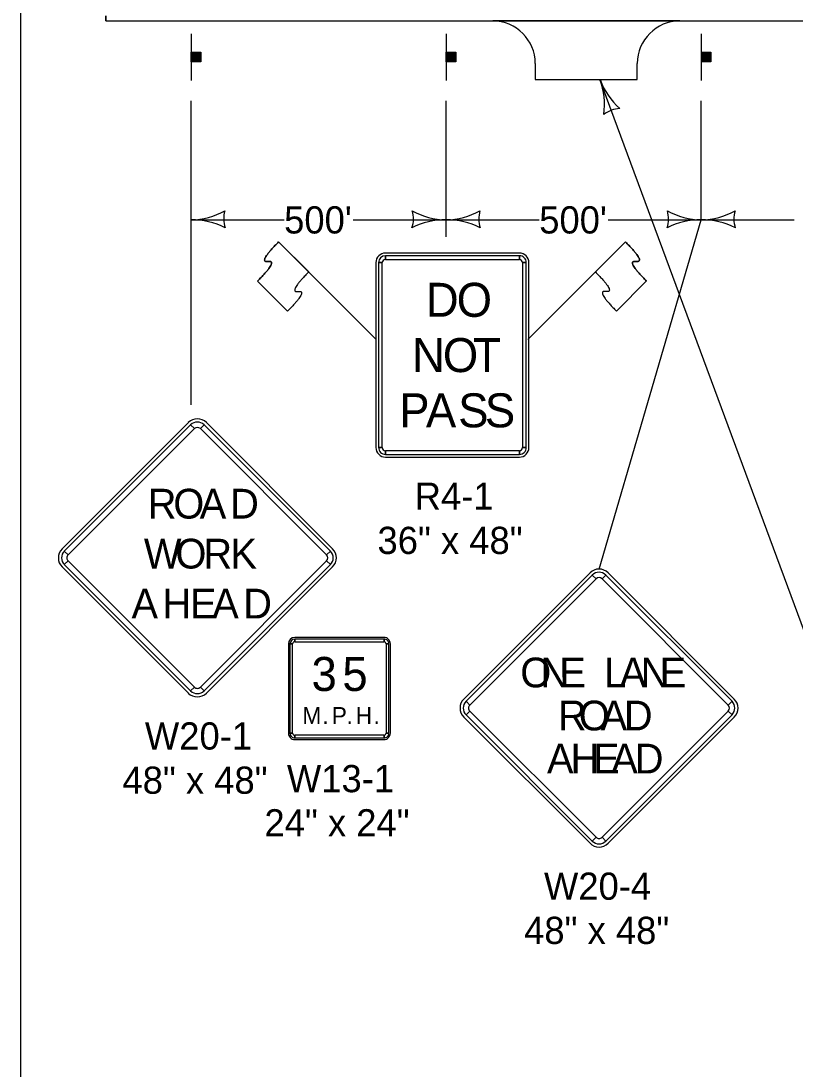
# Model space of a CAD drawing. Extents: x -2134934 to -2119606, y -2139046 to -2137036.
# Drawn here: x -2134934 to -2134479, y -2138285 to -2137668 of the extents above; entities that cross this region are included whole.
import ezdxf

# ---------------------------------------------------------------- set-up
doc = ezdxf.new("R2010")
doc.units = 0
for name, color, linetype in [('Default', 7, 'Continuous'), ('dsnCellElements', 7, 'Continuous'), ('dsnStdLabel', 7, 'Continuous'), ('dsnStdLineWork', 7, 'Continuous'), ('Level 2', 7, 'Continuous'), ('Level 5', 7, 'Continuous')]:
    doc.layers.add(name, color=color, linetype=linetype)

msp = doc.modelspace()

# ---------------------------------------------------------------- linework, layer by layer
at = {"layer": 'Default'}
msp.add_lwpolyline([(-2134934.44, -2137035.95), (-2131799.45, -2137035.95), (-2131799.45, -2139045.94), (-2134934.44, -2139045.94)], close=True, dxfattribs=at)
at = {"layer": 'dsnCellElements'}
for centre, radius, start, end in [((-2134633.81, -2137717.39), 42.5, 352.23545, 20.30794), ((-2134554.09, -2137687.89), 42.5, 200.30794, 228.38043), ((-2134581.58, -2137736.06), 16.42, 92.57459, 128.04129)]:
    msp.add_arc(centre, radius, start, end, dxfattribs=at)
at = {"layer": 'dsnStdLabel'}
for p, q in [((-2134725.6, -2137855.42), (-2134782.94, -2137798.12)), ((-2134782.94, -2137798.12), (-2134765.25, -2137815.8)), ((-2134636.31, -2137855.42), (-2134578.99, -2137798.11)), ((-2134578.99, -2137798.11), (-2134596.67, -2137815.79)), ((-2134641.36, -2137804.67), (-2134720.11, -2137804.67)), ((-2134720.11, -2137808.42), (-2134720.11, -2137806.23)), ((-2134641.36, -2137806.23), (-2134641.36, -2137808.42)), ((-2134725.73, -2137810.29), (-2134725.73, -2137919.04)), ((-2134724.17, -2137810.29), (-2134721.98, -2137810.29)), ((-2134639.48, -2137810.29), (-2134637.3, -2137810.29)), ((-2134635.73, -2137919.04), (-2134635.73, -2137810.29)), ((-2134777.63, -2137838.79), (-2134795.31, -2137821.12)), ((-2134584.29, -2137838.78), (-2134566.61, -2137821.1)), ((-2134836.02, -2137904.4), (-2134910.27, -2137978.64)), ((-2134834.69, -2137905.72), (-2134832.48, -2137907.93)), ((-2134828.95, -2137907.93), (-2134826.74, -2137905.72)), ((-2134751.17, -2137978.64), (-2134825.41, -2137904.4)), ((-2134721.98, -2137919.04), (-2134724.17, -2137919.04)), ((-2134637.3, -2137919.04), (-2134639.48, -2137919.04)), ((-2134720.11, -2137923.1), (-2134720.11, -2137920.91)), ((-2134720.11, -2137924.66), (-2134641.36, -2137924.66)), ((-2134641.36, -2137920.91), (-2134641.36, -2137923.1)), ((-2134906.73, -2137982.18), (-2134908.94, -2137979.97)), ((-2134752.49, -2137979.97), (-2134754.7, -2137982.18)), ((-2134908.94, -2137987.92), (-2134906.73, -2137985.71)), ((-2134754.7, -2137985.71), (-2134752.49, -2137987.92)), ((-2134910.27, -2137989.25), (-2134836.02, -2138063.5)), ((-2134825.41, -2138063.5), (-2134751.17, -2137989.25)), ((-2134599.82, -2137992.73), (-2134674.07, -2138066.98)), ((-2134514.97, -2138066.98), (-2134589.22, -2137992.73)), ((-2134598.5, -2137994.06), (-2134596.29, -2137996.27)), ((-2134592.75, -2137996.27), (-2134590.54, -2137994.06)), ((-2134777.2, -2138034.52), (-2134777.2, -2138087.02)), ((-2134776.26, -2138034.52), (-2134774.7, -2138034.52)), ((-2134720.95, -2138030.77), (-2134773.45, -2138030.77)), ((-2134773.45, -2138033.27), (-2134773.45, -2138031.71)), ((-2134720.95, -2138031.71), (-2134720.95, -2138033.27)), ((-2134719.7, -2138034.52), (-2134718.13, -2138034.52)), ((-2134717.2, -2138087.02), (-2134717.2, -2138034.52)), ((-2134832.48, -2138059.96), (-2134834.69, -2138062.17)), ((-2134826.74, -2138062.17), (-2134828.95, -2138059.96)), ((-2134670.54, -2138070.51), (-2134672.74, -2138068.31)), ((-2134516.3, -2138068.31), (-2134518.51, -2138070.51)), ((-2134674.07, -2138077.59), (-2134599.82, -2138151.83)), ((-2134672.74, -2138076.26), (-2134670.54, -2138074.05)), ((-2134589.22, -2138151.83), (-2134514.97, -2138077.59)), ((-2134518.51, -2138074.05), (-2134516.3, -2138076.26)), ((-2134774.7, -2138087.02), (-2134776.26, -2138087.02)), ((-2134773.45, -2138089.83), (-2134773.45, -2138088.27)), ((-2134773.45, -2138090.77), (-2134720.95, -2138090.77)), ((-2134720.95, -2138088.27), (-2134720.95, -2138089.83)), ((-2134718.13, -2138087.02), (-2134719.7, -2138087.02)), ((-2134596.29, -2138148.3), (-2134598.5, -2138150.51)), ((-2134590.54, -2138150.51), (-2134592.75, -2138148.3))]:
    msp.add_line(p, q, dxfattribs=at)
for points in [[(-2134641.36, -2137806.23), (-2134720.11, -2137806.23), (-2134720.11, -2137808.42), (-2134641.36, -2137808.42), (-2134641.36, -2137806.23)], [(-2134724.17, -2137810.29), (-2134724.17, -2137919.04), (-2134721.98, -2137919.04), (-2134721.98, -2137810.29), (-2134724.17, -2137810.29)], [(-2134637.3, -2137919.04), (-2134637.3, -2137810.29), (-2134639.48, -2137810.29), (-2134639.48, -2137919.04), (-2134637.3, -2137919.04)], [(-2134834.69, -2137905.72), (-2134908.94, -2137979.97), (-2134906.73, -2137982.18), (-2134832.48, -2137907.93), (-2134834.69, -2137905.72)], [(-2134752.49, -2137979.97), (-2134826.74, -2137905.72), (-2134828.95, -2137907.93), (-2134754.7, -2137982.18), (-2134752.49, -2137979.97)], [(-2134720.11, -2137923.1), (-2134641.36, -2137923.1), (-2134641.36, -2137920.91), (-2134720.11, -2137920.91), (-2134720.11, -2137923.1)], [(-2134908.94, -2137987.92), (-2134834.69, -2138062.17), (-2134832.48, -2138059.96), (-2134906.73, -2137985.71), (-2134908.94, -2137987.92)], [(-2134826.74, -2138062.17), (-2134752.49, -2137987.92), (-2134754.7, -2137985.71), (-2134828.95, -2138059.96), (-2134826.74, -2138062.17)], [(-2134598.5, -2137994.06), (-2134672.74, -2138068.31), (-2134670.54, -2138070.51), (-2134596.29, -2137996.27), (-2134598.5, -2137994.06)], [(-2134516.3, -2138068.31), (-2134590.54, -2137994.06), (-2134592.75, -2137996.27), (-2134518.51, -2138070.51), (-2134516.3, -2138068.31)], [(-2134776.26, -2138034.52), (-2134776.26, -2138087.02), (-2134774.7, -2138087.02), (-2134774.7, -2138034.52), (-2134776.26, -2138034.52)], [(-2134720.95, -2138031.71), (-2134773.45, -2138031.71), (-2134773.45, -2138033.27), (-2134720.95, -2138033.27), (-2134720.95, -2138031.71)], [(-2134718.13, -2138087.02), (-2134718.13, -2138034.52), (-2134719.7, -2138034.52), (-2134719.7, -2138087.02), (-2134718.13, -2138087.02)], [(-2134672.74, -2138076.26), (-2134598.5, -2138150.51), (-2134596.29, -2138148.3), (-2134670.54, -2138074.05), (-2134672.74, -2138076.26)], [(-2134590.54, -2138150.51), (-2134516.3, -2138076.26), (-2134518.51, -2138074.05), (-2134592.75, -2138148.3), (-2134590.54, -2138150.51)], [(-2134773.45, -2138089.83), (-2134720.95, -2138089.83), (-2134720.95, -2138088.27), (-2134773.45, -2138088.27), (-2134773.45, -2138089.83)]]:
    msp.add_lwpolyline(points, close=True, dxfattribs=at)
for centre, radius, start, end in [((-2134720.11, -2137810.29), 5.62, 90.00021, 179.99985), ((-2134720.11, -2137810.29), 4.06, 90.00021, 179.99985), ((-2134720.11, -2137810.29), 1.87, 90.00021, 179.99985), ((-2134641.36, -2137810.29), 5.62, 0, 90.00021), ((-2134641.36, -2137810.29), 4.06, 0, 90.00021), ((-2134641.36, -2137810.29), 1.87, 0, 90.00021), ((-2134830.72, -2137909.7), 7.5, 44.99999, 134.99974), ((-2134830.72, -2137909.7), 5.62, 44.99999, 134.99974), ((-2134830.72, -2137909.7), 2.5, 44.99999, 134.99974), ((-2134720.11, -2137919.04), 5.62, 179.99985, 270.00006), ((-2134720.11, -2137919.04), 4.06, 179.99985, 270.00006), ((-2134720.11, -2137919.04), 1.87, 179.99985, 270.00006), ((-2134641.36, -2137919.04), 5.62, 270.00006, 0.00027), ((-2134641.36, -2137919.04), 4.06, 270.00006, 0.00027), ((-2134641.36, -2137919.04), 1.87, 270.00006, 0.00027), ((-2134904.96, -2137983.95), 7.5, 134.99974, 224.99995), ((-2134904.96, -2137983.95), 5.62, 134.99974, 224.99995), ((-2134756.47, -2137983.95), 5.62, 315.00016, 44.9998), ((-2134756.47, -2137983.95), 7.5, 315.00016, 44.9998), ((-2134904.96, -2137983.95), 2.5, 134.99974, 224.99995), ((-2134756.47, -2137983.95), 2.5, 315.00016, 44.9998), ((-2134594.52, -2137998.04), 7.5, 44.99999, 134.99974), ((-2134594.52, -2137998.04), 5.62, 44.99999, 134.99974), ((-2134594.52, -2137998.04), 2.5, 44.99999, 134.99974), ((-2134773.45, -2138034.52), 3.75, 90.00021, 179.99985), ((-2134773.45, -2138034.52), 2.81, 90.00021, 179.99985), ((-2134773.45, -2138034.52), 1.25, 90.00021, 179.99985), ((-2134720.95, -2138034.52), 3.75, 0, 90.00021), ((-2134720.95, -2138034.52), 2.81, 0, 90.00021), ((-2134720.95, -2138034.52), 1.25, 0, 90.00021), ((-2134830.72, -2138058.19), 2.5, 224.99995, 315.00016), ((-2134830.72, -2138058.19), 7.5, 224.99995, 315.00016), ((-2134830.72, -2138058.19), 5.62, 224.99995, 315.00016), ((-2134668.77, -2138072.28), 7.5, 134.99974, 224.99995), ((-2134520.28, -2138072.28), 7.5, 315.00016, 44.9998), ((-2134668.77, -2138072.28), 5.62, 134.99974, 224.99995), ((-2134668.77, -2138072.28), 2.5, 134.99974, 224.99995), ((-2134520.28, -2138072.28), 2.5, 315.00016, 44.9998), ((-2134520.28, -2138072.28), 5.62, 315.00016, 44.9998), ((-2134773.45, -2138087.02), 3.75, 179.99985, 270.00006), ((-2134773.45, -2138087.02), 2.81, 179.99985, 270.00006), ((-2134773.45, -2138087.02), 1.25, 179.99985, 270.00006), ((-2134720.95, -2138087.02), 3.75, 270.00006, 0.00027), ((-2134720.95, -2138087.02), 2.81, 270.00006, 0.00027), ((-2134720.95, -2138087.02), 1.25, 270.00006, 0.00027), ((-2134594.52, -2138146.53), 7.5, 224.99995, 315.00016), ((-2134594.52, -2138146.53), 5.62, 224.99995, 315.00016), ((-2134594.52, -2138146.53), 2.5, 224.99995, 315.00016)]:
    msp.add_arc(centre, radius, start, end, dxfattribs=at)
for points in [[(-2134795.31, -2137821.12), (-2134782.93, -2137808.74), (-2134795.31, -2137810.51), (-2134782.94, -2137798.12)], [(-2134566.61, -2137821.1), (-2134578.99, -2137808.72), (-2134566.61, -2137810.49), (-2134578.99, -2137798.11)], [(-2134765.25, -2137815.8), (-2134777.62, -2137828.19), (-2134765.25, -2137826.41), (-2134777.63, -2137838.79)], [(-2134596.67, -2137815.79), (-2134584.29, -2137828.17), (-2134596.66, -2137826.4), (-2134584.29, -2137838.78)]]:
    msp.add_open_spline(points, degree=2, dxfattribs=at)
at = {"layer": 'dsnStdLineWork'}
for p, q in [((-2134884.44, -2137668.16), (-2134884.44, -2137665.16)), ((-2134884.44, -2137665.16), (-2134884.44, -2137668.16)), ((-2134884.44, -2137668.16), (-2133384.44, -2137668.16)), ((-2134884.44, -2137668.16), (-2133384.44, -2137668.16))]:
    msp.add_line(p, q, dxfattribs=at)
at = {"layer": 'Level 2'}
for p, q in [((-2134547.02, -2137668.16), (-2134657.02, -2137668.16)), ((-2134834.44, -2137675.66), (-2134834.44, -2137703.16)), ((-2134684.44, -2137675.66), (-2134684.44, -2137703.16)), ((-2134534.44, -2137675.66), (-2134534.44, -2137703.16)), ((-2134834.03, -2137692.11), (-2134834.03, -2137686.52)), ((-2134833.75, -2137686.52), (-2134833.75, -2137692.11)), ((-2134833.48, -2137692.11), (-2134833.48, -2137686.52)), ((-2134833.22, -2137686.52), (-2134833.22, -2137692.11)), ((-2134833, -2137692.11), (-2134833, -2137686.52)), ((-2134832.79, -2137686.52), (-2134832.79, -2137692.11)), ((-2134832.45, -2137692.11), (-2134832.45, -2137686.52)), ((-2134832.19, -2137686.52), (-2134832.19, -2137692.11)), ((-2134831.96, -2137692.11), (-2134831.98, -2137686.52)), ((-2134831.65, -2137686.52), (-2134831.65, -2137692.11)), ((-2134831.27, -2137692.11), (-2134831.27, -2137686.52)), ((-2134830.84, -2137686.52), (-2134830.84, -2137692.11)), ((-2134830.61, -2137692.11), (-2134830.63, -2137686.52)), ((-2134830.2, -2137686.52), (-2134830.18, -2137692.11)), ((-2134829.98, -2137692.11), (-2134829.98, -2137686.52)), ((-2134829.66, -2137686.52), (-2134829.66, -2137692.11)), ((-2134829.43, -2137692.11), (-2134829.43, -2137686.52)), ((-2134829.11, -2137686.52), (-2134829.11, -2137692.11)), ((-2134684.03, -2137692.11), (-2134684.03, -2137686.52)), ((-2134683.75, -2137686.52), (-2134683.75, -2137692.11)), ((-2134683.48, -2137692.11), (-2134683.48, -2137686.52)), ((-2134683.22, -2137686.52), (-2134683.22, -2137692.11)), ((-2134683, -2137692.11), (-2134683, -2137686.52)), ((-2134682.79, -2137686.52), (-2134682.79, -2137692.11)), ((-2134682.45, -2137692.11), (-2134682.45, -2137686.52)), ((-2134682.19, -2137686.52), (-2134682.19, -2137692.11)), ((-2134681.97, -2137692.11), (-2134681.98, -2137686.52)), ((-2134681.65, -2137686.52), (-2134681.65, -2137692.11)), ((-2134681.27, -2137692.11), (-2134681.27, -2137686.52)), ((-2134680.84, -2137686.52), (-2134680.84, -2137692.11)), ((-2134680.62, -2137692.11), (-2134680.63, -2137686.52)), ((-2134680.2, -2137686.52), (-2134680.18, -2137692.11)), ((-2134679.98, -2137692.11), (-2134679.98, -2137686.52)), ((-2134679.66, -2137686.52), (-2134679.66, -2137692.11)), ((-2134679.43, -2137692.11), (-2134679.43, -2137686.52)), ((-2134679.12, -2137686.52), (-2134679.12, -2137692.11)), ((-2134534.03, -2137692.11), (-2134534.03, -2137686.52)), ((-2134533.75, -2137686.52), (-2134533.75, -2137692.11)), ((-2134533.48, -2137692.11), (-2134533.48, -2137686.52)), ((-2134533.22, -2137686.52), (-2134533.22, -2137692.11)), ((-2134533, -2137692.11), (-2134533, -2137686.52)), ((-2134532.79, -2137686.52), (-2134532.79, -2137692.11)), ((-2134532.45, -2137692.11), (-2134532.45, -2137686.52)), ((-2134532.19, -2137686.52), (-2134532.19, -2137692.11)), ((-2134531.97, -2137692.11), (-2134531.98, -2137686.52)), ((-2134531.65, -2137686.52), (-2134531.65, -2137692.11)), ((-2134531.27, -2137692.11), (-2134531.27, -2137686.52)), ((-2134530.84, -2137686.52), (-2134530.84, -2137692.11)), ((-2134530.62, -2137692.11), (-2134530.63, -2137686.52)), ((-2134530.2, -2137686.52), (-2134530.18, -2137692.11)), ((-2134529.98, -2137692.11), (-2134529.98, -2137686.52)), ((-2134529.66, -2137686.52), (-2134529.66, -2137692.11)), ((-2134529.43, -2137692.11), (-2134529.43, -2137686.52)), ((-2134529.12, -2137686.52), (-2134529.12, -2137692.11)), ((-2134399.95, -2138226.87), (-2134593.95, -2137702.64)), ((-2134834.44, -2137893.97), (-2134834.44, -2137715.16)), ((-2134684.44, -2137795.16), (-2134684.44, -2137715.16)), ((-2134534.44, -2137785.16), (-2134534.44, -2137715.16)), ((-2134834.44, -2137785.16), (-2134779.69, -2137785.16)), ((-2134739.19, -2137785.16), (-2134684.44, -2137785.16)), ((-2134684.44, -2137785.16), (-2134629.69, -2137785.16)), ((-2134594.52, -2137990.54), (-2134534.44, -2137785.16)), ((-2134589.19, -2137785.16), (-2134534.44, -2137785.16)), ((-2134534.44, -2137785.16), (-2134479.69, -2137785.16))]:
    msp.add_line(p, q, dxfattribs=at)
for points in [[(-2134834.35, -2137692.11), (-2134834.35, -2137686.48), (-2134828.72, -2137686.48), (-2134828.72, -2137692.11)], [(-2134684.35, -2137692.11), (-2134684.35, -2137686.48), (-2134678.72, -2137686.48), (-2134678.72, -2137692.11)], [(-2134534.35, -2137692.11), (-2134534.35, -2137686.48), (-2134528.72, -2137686.48), (-2134528.72, -2137692.11)]]:
    msp.add_lwpolyline(points, close=True, dxfattribs=at)
msp.add_lwpolyline([(-2134632.02, -2137693.16), (-2134632.02, -2137702.65), (-2134572.02, -2137702.65), (-2134572.02, -2137693.16)], dxfattribs=at)
for centre, radius, start, end in [((-2134657.02, -2137693.16), 25, 0, 90), ((-2134547.02, -2137693.16), 25, 90, 180), ((-2134835.2, -2137742.67), 42.5, 271.0176, 299.07249), ((-2134798.82, -2137784.54), 16.42, 163.26665, 198.73335), ((-2134720.06, -2137784.54), 16.42, 341.26665, 16.73335), ((-2134683.69, -2137742.67), 42.5, 240.92751, 268.9824), ((-2134685.2, -2137742.67), 42.5, 271.0176, 299.07249), ((-2134648.82, -2137784.54), 16.42, 163.26665, 198.73335), ((-2134570.06, -2137784.54), 16.42, 341.26665, 16.73335), ((-2134533.69, -2137742.67), 42.5, 240.92751, 268.9824), ((-2134535.2, -2137742.67), 42.5, 271.0176, 299.07249), ((-2134498.82, -2137784.54), 16.42, 163.26665, 198.73335), ((-2134833.71, -2137827.65), 42.5, 62.92751, 90.9824), ((-2134685.17, -2137827.65), 42.5, 89.0176, 117.07249), ((-2134683.71, -2137827.65), 42.5, 62.92751, 90.9824), ((-2134535.17, -2137827.65), 42.5, 89.0176, 117.07249), ((-2134533.71, -2137827.65), 42.5, 62.92751, 90.9824)]:
    msp.add_arc(centre, radius, start, end, dxfattribs=at)
at = {"layer": 'Level 5'}
for p, q in [((-2134795.31, -2137821.12), (-2134777.63, -2137838.79)), ((-2134566.61, -2137821.1), (-2134584.29, -2137838.78))]:
    msp.add_line(p, q, dxfattribs=at)
for points in [[(-2134782.94, -2137798.12), (-2134795.31, -2137810.51), (-2134782.93, -2137808.74), (-2134795.31, -2137821.12)], [(-2134578.99, -2137798.11), (-2134566.61, -2137810.49), (-2134578.99, -2137808.72), (-2134566.61, -2137821.1)], [(-2134765.25, -2137815.8), (-2134777.62, -2137828.19), (-2134765.25, -2137826.41), (-2134777.63, -2137838.79)], [(-2134596.67, -2137815.79), (-2134584.29, -2137828.17), (-2134596.66, -2137826.4), (-2134584.29, -2137838.78)]]:
    msp.add_open_spline(points, degree=2, dxfattribs=at)

# ---------------------------------------------------------------- texts
at = {"layer": 'dsnStdLabel'}
for s, height, p in [('D', 20, (-2134696.36, -2137842.17)), ('O', 20, (-2134678.23, -2137842.17)), ('N', 20, (-2134704.48, -2137874.67)), ('O', 20, (-2134686.36, -2137874.67)), ('T', 20, (-2134668.55, -2137874.67)), ('P', 20, (-2134712, -2137907.17)), ('A', 20, (-2134696.31, -2137907.17)), ('S', 20, (-2134677.34, -2137907.17)), ('S', 20, (-2134661.66, -2137907.17)), ('R', 17.5, (-2134859.88, -2137960.82)), ('O', 17.5, (-2134844.87, -2137960.82)), ('A', 17.5, (-2134829.32, -2137960.82)), ('D', 17.5, (-2134811.44, -2137960.82)), ('R4-1', 16, (-2134702.9, -2137955.66)), ('36" x 48"', 16, (-2134724.8, -2137981.66)), ('W', 17.5, (-2134862.16, -2137990.2)), ('O', 17.5, (-2134843.57, -2137990.2)), ('R', 17.5, (-2134827.16, -2137990.2)), ('K', 17.5, (-2134811.3, -2137990.2)), ('A', 17.5, (-2134869.44, -2138019.57)), ('H', 17.5, (-2134851.23, -2138019.57)), ('E', 17.5, (-2134835, -2138019.57)), ('A', 17.5, (-2134821.96, -2138019.57)), ('D', 17.5, (-2134803.75, -2138019.57)), ('3', 20, (-2134763.58, -2138062.23)), ('5', 20, (-2134745.46, -2138062.23)), ('O', 17.5, (-2134640.81, -2138060.1)), ('N', 17.5, (-2134629.03, -2138060.1)), ('E', 17.5, (-2134617.8, -2138060.1)), ('L', 17.5, (-2134591.55, -2138060.1)), ('A', 17.5, (-2134582.36, -2138060.1)), ('N', 17.5, (-2134570.09, -2138060.1)), ('E', 17.5, (-2134558.86, -2138060.1)), ('M', 10, (-2134768.97, -2138081.71)), ('P', 10, (-2134751.72, -2138081.71)), ('H', 10, (-2134737.6, -2138081.71)), ('R', 17.5, (-2134618.7, -2138085.41)), ('O', 17.5, (-2134606.41, -2138085.41)), ('A', 17.5, (-2134593.57, -2138085.41)), ('D', 17.5, (-2134579.92, -2138085.41)), ('W20-1', 16, (-2134861.57, -2138096.69)), ('.', 10, (-2134757.18, -2138081.71)), ('.', 10, (-2134743.06, -2138081.71)), ('.', 10, (-2134727.13, -2138081.71)), ('A', 17.5, (-2134625.14, -2138110.72)), ('H', 17.5, (-2134611.27, -2138110.72)), ('E', 17.5, (-2134598.05, -2138110.72)), ('A', 17.5, (-2134587.34, -2138110.72)), ('D', 17.5, (-2134573.48, -2138110.72)), ('48" x 48"', 16, (-2134874.78, -2138122.69)), ('W13-1', 16, (-2134778.05, -2138121.77)), ('24" x 24"', 16, (-2134791.26, -2138147.77)), ('W20-4', 16, (-2134626.89, -2138185.03)), ('48" x 48"', 16, (-2134638.59, -2138211.03))]:
    msp.add_text(s, height=height, dxfattribs=at).set_placement(p)
at = {"layer": 'Level 2'}
for p in [(-2134779.69, -2137793.16), (-2134629.69, -2137793.16)]:
    msp.add_text("500'", height=16, dxfattribs=at).set_placement(p)

doc.saveas('drawing.dxf')
